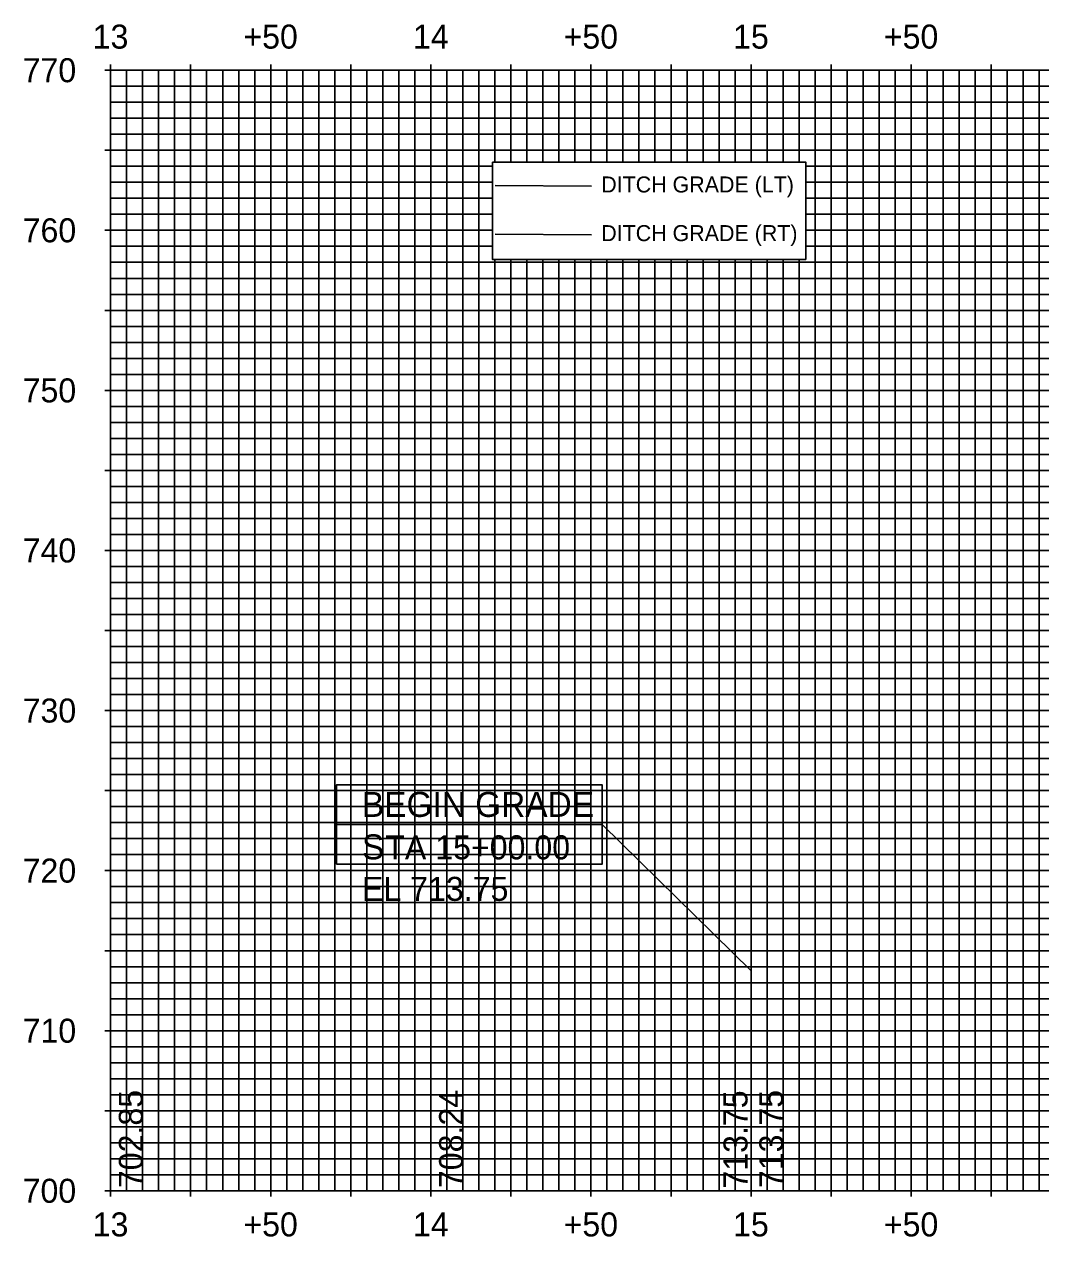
# Model space of a CAD drawing. Extents: x 273 to 1727, y 687 to 1144.
# Drawn here: x 273 to 590.5, y 765.6 to 1144.4 of the extents above; entities that cross this region are included whole.
import ezdxf

# ---------------------------------------------------------------- set-up
doc = ezdxf.new("R2010")
doc.units = 0
for name, color, linetype in [('Catch Basin Box 24 Dia-Bottom CELL', 7, 'Continuous'), ('Construction Elements LEVEL', 7, 'Continuous'), ('Cut Ditch Special with Hinge Detail CELL', 7, 'Continuous'), ('Drop Inlet Box Type B 36 Dia-Bottom CELL', 7, 'Continuous'), ('Drop Inlet Grate 2 Narrow Slot and Flat Grates 840 29 36 Dia BD-Top CELL', 7, 'Continuous'), ('Drop Inlet Grate 2 Wide Slot and Flat Grates 840 20 36 Dia BD CELL', 7, 'Continuous'), ('Drop Inlet Grate 840 16 CELL', 7, 'Continuous'), ('E_HYD_Watershed_Grass_C_03', 7, 'Continuous'), ('E_NCDOT_Vertical_Profile_Ground_Line', 7, 'Continuous'), ('Exist Roads EOP', 7, 'Continuous'), ('P_HYD_Drop_Inlet_Box_Type_B_36_Dia-Bottom_CELL', 7, 'Continuous'), ('P_NCDOT_SS_Cut_Line', 7, 'Continuous'), ('P_NCDOT_SS_Transition_Line', 7, 'Continuous')]:
    doc.layers.add(name, color=color, linetype=linetype)

msp = doc.modelspace()

# ---------------------------------------------------------------- linework, layer by layer
at = {"layer": 'Construction Elements LEVEL'}
for p, q in [((350, 780), (350, 1130)), ((400, 780), (400, 1130)), ((450, 1101.31), (450, 1130)), ((500, 1101.31), (500, 1130)), ((550, 780), (550, 1130)), ((300, 1080), (419.21, 1080)), ((517.06, 1080), (1700, 1080)), ((450, 780), (450, 1070.91)), ((500, 780), (500, 1070.91)), ((300, 1030), (1700, 1030)), ((300, 980), (1700, 980)), ((300, 930), (1700, 930)), ((300, 880), (1700, 880)), ((300, 830), (1700, 830)), ((300, 780), (1700, 780)), ((300, 780), (1700, 780))]:
    msp.add_line(p, q, dxfattribs=at)
at = {"layer": 'Cut Ditch Special with Hinge Detail CELL'}
msp.add_line((420.05, 1078.79), (450.21, 1078.58), dxfattribs=at)
at = {"layer": 'Drop Inlet Box Type B 36 Dia-Bottom CELL'}
for p, q in [((370.51, 894.41), (453.55, 894.45)), ((453.55, 894.45), (500, 848.75))]:
    msp.add_line(p, q, dxfattribs=at)
msp.add_lwpolyline([(370.51, 882.04), (453.55, 882.04), (453.55, 906.77), (370.51, 906.77)], close=True, dxfattribs=at)
at = {"layer": 'Drop Inlet Grate 2 Wide Slot and Flat Grates 840 20 36 Dia BD CELL'}
msp.add_line((420.05, 1093.99), (450.21, 1093.78), dxfattribs=at)
at = {"layer": 'E_HYD_Watershed_Grass_C_03'}
msp.add_lwpolyline([(419.21, 1101.31), (517.06, 1101.31), (517.06, 1070.91), (419.21, 1070.91)], close=True, dxfattribs=at)
at = {"layer": 'E_NCDOT_Vertical_Profile_Ground_Line'}
for p, q in [((305, 780), (305, 1130)), ((310, 780), (310, 1130)), ((315, 780), (315, 1130)), ((320, 780), (320, 1130)), ((330, 780), (330, 1130)), ((335, 780), (335, 1130)), ((340, 780), (340, 1130)), ((345, 780), (345, 1130)), ((355, 780), (355, 1130)), ((360, 780), (360, 1130)), ((365, 780), (365, 1130)), ((370, 780), (370, 1130)), ((380, 780), (380, 1130)), ((385, 780), (385, 1130)), ((390, 780), (390, 1130)), ((395, 780), (395, 1130)), ((405, 780), (405, 1130)), ((410, 780), (410, 1130)), ((415, 780), (415, 1130)), ((420, 1101.31), (420, 1130)), ((430, 1101.31), (430, 1130)), ((435, 1101.31), (435, 1130)), ((440, 1101.31), (440, 1130)), ((445, 1101.31), (445, 1130)), ((455, 1101.31), (455, 1130)), ((460, 1101.31), (460, 1130)), ((465, 1101.31), (465, 1130)), ((470, 1101.31), (470, 1130)), ((480, 1101.31), (480, 1130)), ((485, 1101.31), (485, 1130)), ((490, 1101.31), (490, 1130)), ((495, 1101.31), (495, 1130)), ((505, 1101.31), (505, 1130)), ((510, 1101.31), (510, 1130)), ((515, 1101.31), (515, 1130)), ((520, 780), (520, 1130)), ((530, 780), (530, 1130)), ((535, 780), (535, 1130)), ((540, 780), (540, 1130)), ((545, 780), (545, 1130)), ((555, 780), (555, 1130)), ((560, 780), (560, 1130)), ((565, 780), (565, 1130)), ((570, 780), (570, 1130)), ((580, 780), (580, 1130)), ((585, 780), (585, 1130)), ((590, 780), (590, 1130)), ((300, 1125), (1700, 1125)), ((300, 1120), (1700, 1120)), ((300, 1115), (1700, 1115)), ((300, 1110), (1700, 1110)), ((300, 1100), (419.21, 1100)), ((517.06, 1100), (1700, 1100)), ((300, 1095), (419.21, 1095)), ((517.06, 1095), (1700, 1095)), ((300, 1090), (419.21, 1090)), ((517.06, 1090), (1700, 1090)), ((300, 1085), (419.21, 1085)), ((517.06, 1085), (1700, 1085)), ((300, 1075), (419.21, 1075)), ((517.06, 1075), (1700, 1075)), ((300, 1070), (1700, 1070)), ((420, 780), (420, 1070.91)), ((430, 780), (430, 1070.91)), ((435, 780), (435, 1070.91)), ((440, 780), (440, 1070.91)), ((445, 780), (445, 1070.91)), ((455, 780), (455, 1070.91)), ((460, 780), (460, 1070.91)), ((465, 780), (465, 1070.91)), ((470, 780), (470, 1070.91)), ((480, 780), (480, 1070.91)), ((485, 780), (485, 1070.91)), ((490, 780), (490, 1070.91)), ((495, 780), (495, 1070.91)), ((505, 780), (505, 1070.91)), ((510, 780), (510, 1070.91)), ((515, 780), (515, 1070.91)), ((300, 1065), (1700, 1065)), ((300, 1060), (1700, 1060)), ((300, 1050), (1700, 1050)), ((300, 1045), (1700, 1045)), ((300, 1040), (1700, 1040)), ((300, 1035), (1700, 1035)), ((300, 1025), (1700, 1025)), ((300, 1020), (1700, 1020)), ((300, 1015), (1700, 1015)), ((300, 1010), (1700, 1010)), ((300, 1000), (1700, 1000)), ((300, 995), (1700, 995)), ((300, 990), (1700, 990)), ((300, 985), (1700, 985)), ((300, 975), (1700, 975)), ((300, 970), (1700, 970)), ((300, 965), (1700, 965)), ((300, 960), (1700, 960)), ((300, 950), (1700, 950)), ((300, 945), (1700, 945)), ((300, 940), (1700, 940)), ((300, 935), (1700, 935)), ((300, 925), (1700, 925)), ((300, 920), (1700, 920)), ((300, 915), (1700, 915)), ((300, 910), (1700, 910)), ((300, 900), (1700, 900)), ((300, 895), (1700, 895)), ((300, 890), (1700, 890)), ((300, 885), (1700, 885)), ((300, 875), (1700, 875)), ((300, 870), (1700, 870)), ((300, 865), (1700, 865)), ((300, 860), (1700, 860)), ((300, 850), (1700, 850)), ((300, 845), (1700, 845)), ((300, 840), (1700, 840)), ((300, 835), (1700, 835)), ((300, 825), (1700, 825)), ((300, 820), (1700, 820)), ((300, 815), (1700, 815)), ((300, 815), (1700, 815)), ((300, 810), (1700, 810)), ((300, 810), (1700, 810)), ((300, 800), (1700, 800)), ((300, 800), (1700, 800)), ((300, 795), (1700, 795)), ((300, 795), (1700, 795)), ((300, 790), (1700, 790)), ((300, 790), (1700, 790)), ((300, 785), (1700, 785)), ((300, 785), (1700, 785))]:
    msp.add_line(p, q, dxfattribs=at)
at = {"layer": 'P_NCDOT_SS_Cut_Line'}
for p, q in [((300, 1130), (298.2, 1130)), ((300, 1131.8), (300, 1130)), ((325, 1131.8), (325, 1130)), ((325, 780), (325, 1130)), ((350, 1131.8), (350, 1130)), ((350, 780), (350, 1130)), ((375, 1131.8), (375, 1130)), ((375, 780), (375, 1130)), ((400, 1131.8), (400, 1130)), ((400, 780), (400, 1130)), ((425, 1131.8), (425, 1130)), ((425, 1101.31), (425, 1130)), ((450, 1131.8), (450, 1130)), ((450, 1101.31), (450, 1130)), ((475, 1131.8), (475, 1130)), ((475, 1101.31), (475, 1130)), ((500, 1131.8), (500, 1130)), ((500, 1101.31), (500, 1130)), ((525, 1131.8), (525, 1130)), ((525, 780), (525, 1130)), ((550, 1131.8), (550, 1130)), ((550, 780), (550, 1130)), ((575, 1131.8), (575, 1130)), ((575, 780), (575, 1130)), ((300, 1105), (298.2, 1105)), ((300, 1105), (1700, 1105)), ((300, 1080), (298.2, 1080)), ((300, 1080), (419.21, 1080)), ((517.06, 1080), (1700, 1080)), ((425, 780), (425, 1070.91)), ((450, 780), (450, 1070.91)), ((475, 780), (475, 1070.91)), ((500, 780), (500, 1070.91)), ((300, 1055), (298.2, 1055)), ((300, 1055), (1700, 1055)), ((300, 1030), (298.2, 1030)), ((300, 1030), (1700, 1030)), ((300, 1005), (298.2, 1005)), ((300, 1005), (1700, 1005)), ((300, 980), (298.2, 980)), ((300, 980), (1700, 980)), ((300, 955), (298.2, 955)), ((300, 955), (1700, 955)), ((300, 930), (298.2, 930)), ((300, 930), (1700, 930)), ((300, 905), (298.2, 905)), ((300, 905), (1700, 905)), ((300, 880), (298.2, 880)), ((300, 880), (1700, 880)), ((300, 855), (298.2, 855)), ((300, 855), (1700, 855)), ((300, 830), (298.2, 830)), ((300, 830), (1700, 830)), ((300, 805), (298.2, 805)), ((300, 805), (298.2, 805)), ((300, 805), (298.2, 805)), ((300, 805), (1700, 805)), ((300, 805), (1700, 805)), ((300, 780), (298.2, 780)), ((300, 780), (298.2, 780)), ((300, 780), (298.2, 780)), ((300, 780), (300, 778.2)), ((300, 780), (1700, 780)), ((300, 780), (1700, 780)), ((325, 780), (325, 778.2)), ((350, 780), (350, 778.2)), ((375, 780), (375, 778.2)), ((400, 780), (400, 778.2)), ((425, 780), (425, 778.2)), ((450, 780), (450, 778.2)), ((475, 780), (475, 778.2)), ((500, 780), (500, 778.2)), ((525, 780), (525, 778.2)), ((550, 780), (550, 778.2)), ((575, 780), (575, 778.2))]:
    msp.add_line(p, q, dxfattribs=at)
at = {"layer": 'P_NCDOT_SS_Transition_Line'}
for p, q in [((300, 1130), (1700, 1130)), ((300, 780), (300, 1130)), ((300, 780), (1700, 780))]:
    msp.add_line(p, q, dxfattribs=at)

# ---------------------------------------------------------------- texts
at = {"layer": 'Catch Basin Box 24 Dia-Bottom CELL'}
for s, p in [('13', (294.41, 1136.75)), ('+50', (341.46, 1136.75)), ('14', (394.43, 1136.75)), ('+50', (441.46, 1136.75)), ('15', (494.38, 1136.75)), ('+50', (541.46, 1136.75)), ('13', (294.41, 765.75)), ('+50', (341.46, 765.75)), ('14', (394.43, 765.75)), ('+50', (441.46, 765.75)), ('15', (494.38, 765.75)), ('+50', (541.46, 765.75))]:
    msp.add_text(s, height=7.5, dxfattribs=at).set_placement(p)
at = {"layer": 'Drop Inlet Box Type B 36 Dia-Bottom CELL'}
for s, height, p in [('BEGIN GRADE ', 7.8, (378.5, 896.78)), ('S', 7.8, (378.5, 883.52)), ('TA 15+00.00', 7.5, (385.77, 883.52)), ('EL 713.75', 7.5, (378.5, 870.56))]:
    msp.add_text(s, height=height, dxfattribs=at).set_placement(p)
at = {"layer": 'Drop Inlet Grate 2 Narrow Slot and Flat Grates 840 29 36 Dia BD-Top CELL'}
for s, p in [('702.85', (310.08, 780.84)), ('708.24', (410.08, 780.84)), ('713.75', (510.06, 780.84))]:
    msp.add_text(s, height=7.5, rotation=90, dxfattribs=at).set_placement(p)
at = {"layer": 'Drop Inlet Grate 840 16 CELL'}
for s, p in [('770', (272.53, 1126.25)), ('760', (272.53, 1076.25)), ('750', (272.53, 1026.25)), ('740', (272.53, 976.25)), ('730', (272.53, 926.25)), ('720', (272.53, 876.25)), ('710', (272.53, 826.25)), ('700', (272.53, 776.25))]:
    msp.add_text(s, height=7.5, dxfattribs=at).set_placement(p)
at = {"layer": 'Exist Roads EOP'}
for s, p in [('DITCH GRADE (LT)', (453.21, 1091.82)), ('DITCH GRADE (RT)', (453.21, 1076.62))]:
    msp.add_text(s, height=5, dxfattribs=at).set_placement(p)
at = {"layer": 'P_HYD_Drop_Inlet_Box_Type_B_36_Dia-Bottom_CELL'}
msp.add_text('713.75', height=7.5, rotation=90, dxfattribs=at).set_placement((498.89, 780.67))

doc.saveas('drawing.dxf')
